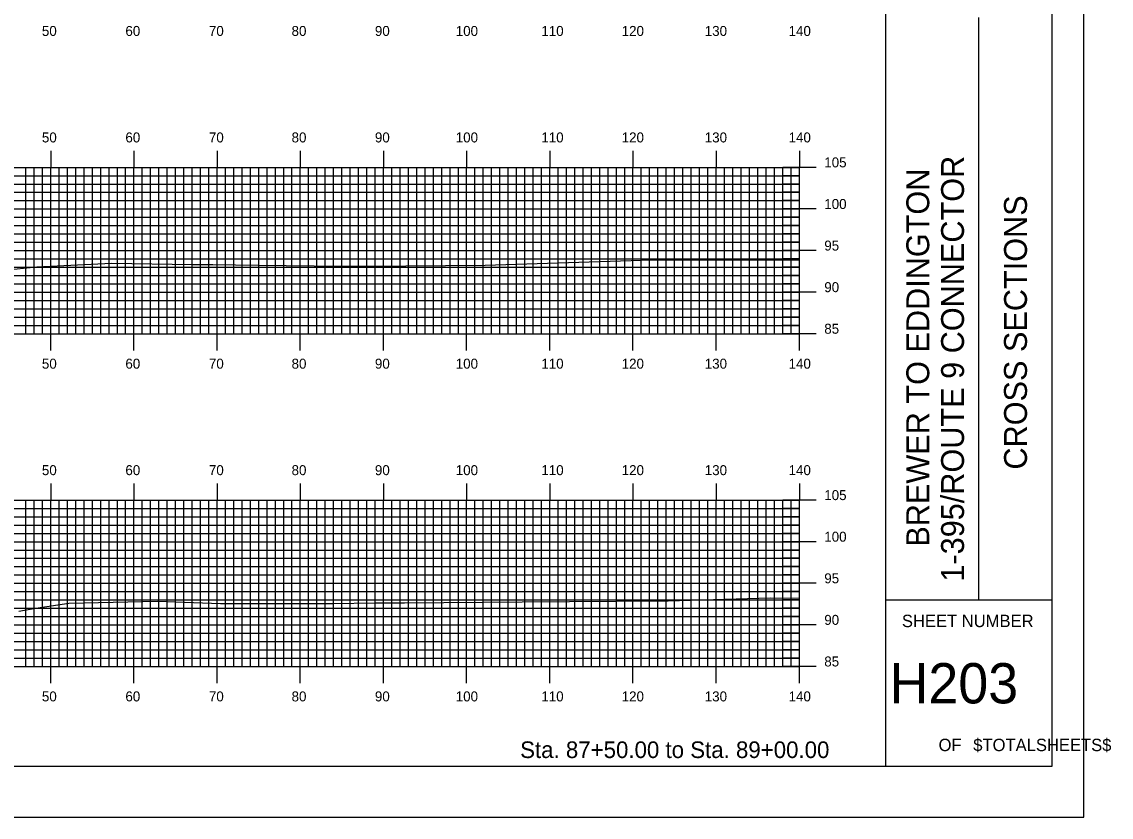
# Model space of a CAD drawing. Extents: x 1764152 to 1764495, y 442591 to 442811.
# Drawn here: x 1764364.3 to 1764495.3, y 442590.5 to 442686.2 of the extents above; entities that cross this region are included whole.
import ezdxf

# ---------------------------------------------------------------- set-up
doc = ezdxf.new("R2010")
doc.units = 0
for name, color, linetype in [('BORDER', 7, 'Continuous'), ('H_V ANNOTATION', 7, 'Continuous'), ('MAJOR', 7, 'Continuous'), ('MINOR', 7, 'Continuous'), ('PLOT BOUNDARY', 7, 'Continuous'), ('S_Roadway_Centerline', 7, 'Continuous')]:
    doc.layers.add(name, color=color, linetype=linetype)

msp = doc.modelspace()

# ---------------------------------------------------------------- linework, layer by layer
at = {"layer": 'BORDER'}
for p, q in [((1764468.23, 442596.67), (1764468.23, 442806.67)), ((1764479.41, 442616.67), (1764479.41, 442686.67)), ((1764468.23, 442616.67), (1764488.23, 442616.67))]:
    msp.add_line(p, q, dxfattribs=at)
msp.add_lwpolyline([(1764168.23, 442596.67), (1764488.23, 442596.67), (1764488.23, 442806.67), (1764168.23, 442806.67)], close=True, dxfattribs=at)
at = {"layer": 'MAJOR'}
for p, q in [((1764367.83, 442670.67), (1764367.83, 442668.67)), ((1764377.83, 442670.67), (1764377.83, 442668.67)), ((1764387.83, 442670.67), (1764387.83, 442668.67)), ((1764397.83, 442670.67), (1764397.83, 442668.67)), ((1764407.83, 442670.67), (1764407.83, 442668.67)), ((1764417.83, 442670.67), (1764417.83, 442668.67)), ((1764427.83, 442670.67), (1764427.83, 442668.67)), ((1764437.83, 442670.67), (1764437.83, 442668.67)), ((1764447.83, 442670.67), (1764447.83, 442668.67)), ((1764457.83, 442670.67), (1764457.83, 442668.67)), ((1764177.83, 442668.67), (1764457.83, 442668.67)), ((1764177.83, 442668.67), (1764457.83, 442668.67)), ((1764367.83, 442648.67), (1764367.83, 442668.67)), ((1764377.83, 442648.67), (1764377.83, 442668.67)), ((1764387.83, 442648.67), (1764387.83, 442668.67)), ((1764397.83, 442648.67), (1764397.83, 442668.67)), ((1764407.83, 442648.67), (1764407.83, 442668.67)), ((1764417.83, 442648.67), (1764417.83, 442668.67)), ((1764427.83, 442648.67), (1764427.83, 442668.67)), ((1764437.83, 442648.67), (1764437.83, 442668.67)), ((1764447.83, 442648.67), (1764447.83, 442668.67)), ((1764459.84, 442668.67), (1764455.83, 442668.67)), ((1764457.83, 442648.67), (1764457.83, 442668.67)), ((1764457.83, 442648.67), (1764457.83, 442668.67)), ((1764177.83, 442663.67), (1764457.83, 442663.67)), ((1764459.84, 442663.67), (1764455.83, 442663.67)), ((1764177.83, 442658.67), (1764457.83, 442658.67)), ((1764459.84, 442658.67), (1764455.83, 442658.67)), ((1764177.83, 442653.67), (1764457.83, 442653.67)), ((1764459.84, 442653.67), (1764455.83, 442653.67)), ((1764177.83, 442648.67), (1764457.83, 442648.67)), ((1764177.83, 442648.67), (1764457.83, 442648.67)), ((1764367.83, 442646.66), (1764367.83, 442648.67)), ((1764377.83, 442646.66), (1764377.83, 442648.67)), ((1764387.83, 442646.66), (1764387.83, 442648.67)), ((1764397.83, 442646.66), (1764397.83, 442648.67)), ((1764407.83, 442646.66), (1764407.83, 442648.67)), ((1764417.83, 442646.66), (1764417.83, 442648.67)), ((1764427.83, 442646.66), (1764427.83, 442648.67)), ((1764437.83, 442646.66), (1764437.83, 442648.67)), ((1764447.83, 442646.66), (1764447.83, 442648.67)), ((1764459.84, 442648.67), (1764455.83, 442648.67)), ((1764457.83, 442646.66), (1764457.83, 442648.67)), ((1764367.83, 442630.67), (1764367.83, 442628.67)), ((1764377.83, 442630.67), (1764377.83, 442628.67)), ((1764387.83, 442630.67), (1764387.83, 442628.67)), ((1764397.83, 442630.67), (1764397.83, 442628.67)), ((1764407.83, 442630.67), (1764407.83, 442628.67)), ((1764417.83, 442630.67), (1764417.83, 442628.67)), ((1764427.83, 442630.67), (1764427.83, 442628.67)), ((1764437.83, 442630.67), (1764437.83, 442628.67)), ((1764447.83, 442630.67), (1764447.83, 442628.67)), ((1764457.83, 442630.67), (1764457.83, 442628.67)), ((1764177.83, 442628.67), (1764457.83, 442628.67)), ((1764177.83, 442628.67), (1764457.83, 442628.67)), ((1764367.83, 442608.67), (1764367.83, 442628.67)), ((1764377.83, 442608.67), (1764377.83, 442628.67)), ((1764387.83, 442608.67), (1764387.83, 442628.67)), ((1764397.83, 442608.67), (1764397.83, 442628.67)), ((1764407.83, 442608.67), (1764407.83, 442628.67)), ((1764417.83, 442608.67), (1764417.83, 442628.67)), ((1764427.83, 442608.67), (1764427.83, 442628.67)), ((1764437.83, 442608.67), (1764437.83, 442628.67)), ((1764447.83, 442608.67), (1764447.83, 442628.67)), ((1764459.84, 442628.67), (1764455.83, 442628.67)), ((1764457.83, 442608.67), (1764457.83, 442628.67)), ((1764457.83, 442608.67), (1764457.83, 442628.67)), ((1764177.83, 442623.67), (1764457.83, 442623.67)), ((1764459.84, 442623.67), (1764455.83, 442623.67)), ((1764177.83, 442618.67), (1764457.83, 442618.67)), ((1764459.84, 442618.67), (1764455.83, 442618.67)), ((1764177.83, 442613.67), (1764457.83, 442613.67)), ((1764459.84, 442613.67), (1764455.83, 442613.67)), ((1764177.83, 442608.67), (1764457.83, 442608.67)), ((1764177.83, 442608.67), (1764457.83, 442608.67)), ((1764367.83, 442606.66), (1764367.83, 442608.67)), ((1764377.83, 442606.66), (1764377.83, 442608.67)), ((1764387.83, 442606.66), (1764387.83, 442608.67)), ((1764397.83, 442606.66), (1764397.83, 442608.67)), ((1764407.83, 442606.66), (1764407.83, 442608.67)), ((1764417.83, 442606.66), (1764417.83, 442608.67)), ((1764427.83, 442606.66), (1764427.83, 442608.67)), ((1764437.83, 442606.66), (1764437.83, 442608.67)), ((1764447.83, 442606.66), (1764447.83, 442608.67)), ((1764459.84, 442608.67), (1764455.83, 442608.67)), ((1764457.83, 442606.66), (1764457.83, 442608.67))]:
    msp.add_line(p, q, dxfattribs=at)
at = {"layer": 'MINOR'}
for p, q in [((1764364.83, 442648.67), (1764364.83, 442668.67)), ((1764365.83, 442648.67), (1764365.83, 442668.67)), ((1764366.83, 442648.67), (1764366.83, 442668.67)), ((1764368.83, 442648.67), (1764368.83, 442668.67)), ((1764369.83, 442648.67), (1764369.83, 442668.67)), ((1764370.83, 442648.67), (1764370.83, 442668.67)), ((1764371.83, 442648.67), (1764371.83, 442668.67)), ((1764372.83, 442648.67), (1764372.83, 442668.67)), ((1764373.83, 442648.67), (1764373.83, 442668.67)), ((1764374.83, 442648.67), (1764374.83, 442668.67)), ((1764375.83, 442648.67), (1764375.83, 442668.67)), ((1764376.83, 442648.67), (1764376.83, 442668.67)), ((1764378.83, 442648.67), (1764378.83, 442668.67)), ((1764379.83, 442648.67), (1764379.83, 442668.67)), ((1764380.83, 442648.67), (1764380.83, 442668.67)), ((1764381.83, 442648.67), (1764381.83, 442668.67)), ((1764382.83, 442648.67), (1764382.83, 442668.67)), ((1764383.83, 442648.67), (1764383.83, 442668.67)), ((1764384.83, 442648.67), (1764384.83, 442668.67)), ((1764385.83, 442648.67), (1764385.83, 442668.67)), ((1764386.83, 442648.67), (1764386.83, 442668.67)), ((1764388.83, 442648.67), (1764388.83, 442668.67)), ((1764389.83, 442648.67), (1764389.83, 442668.67)), ((1764390.83, 442648.67), (1764390.83, 442668.67)), ((1764391.83, 442648.67), (1764391.83, 442668.67)), ((1764392.83, 442648.67), (1764392.83, 442668.67)), ((1764393.83, 442648.67), (1764393.83, 442668.67)), ((1764394.83, 442648.67), (1764394.83, 442668.67)), ((1764395.83, 442648.67), (1764395.83, 442668.67)), ((1764396.83, 442648.67), (1764396.83, 442668.67)), ((1764398.83, 442648.67), (1764398.83, 442668.67)), ((1764399.83, 442648.67), (1764399.83, 442668.67)), ((1764400.83, 442648.67), (1764400.83, 442668.67)), ((1764401.83, 442648.67), (1764401.83, 442668.67)), ((1764402.83, 442648.67), (1764402.83, 442668.67)), ((1764403.83, 442648.67), (1764403.83, 442668.67)), ((1764404.83, 442648.67), (1764404.83, 442668.67)), ((1764405.83, 442648.67), (1764405.83, 442668.67)), ((1764406.83, 442648.67), (1764406.83, 442668.67)), ((1764408.83, 442648.67), (1764408.83, 442668.67)), ((1764409.83, 442648.67), (1764409.83, 442668.67)), ((1764410.83, 442648.67), (1764410.83, 442668.67)), ((1764411.83, 442648.67), (1764411.83, 442668.67)), ((1764412.83, 442648.67), (1764412.83, 442668.67)), ((1764413.83, 442648.67), (1764413.83, 442668.67)), ((1764414.83, 442648.67), (1764414.83, 442668.67)), ((1764415.83, 442648.67), (1764415.83, 442668.67)), ((1764416.83, 442648.67), (1764416.83, 442668.67)), ((1764418.83, 442648.67), (1764418.83, 442668.67)), ((1764419.83, 442648.67), (1764419.83, 442668.67)), ((1764420.83, 442648.67), (1764420.83, 442668.67)), ((1764421.83, 442648.67), (1764421.83, 442668.67)), ((1764422.83, 442648.67), (1764422.83, 442668.67)), ((1764423.83, 442648.67), (1764423.83, 442668.67)), ((1764424.83, 442648.67), (1764424.83, 442668.67)), ((1764425.83, 442648.67), (1764425.83, 442668.67)), ((1764426.83, 442648.67), (1764426.83, 442668.67)), ((1764428.83, 442648.67), (1764428.83, 442668.67)), ((1764429.83, 442648.67), (1764429.83, 442668.67)), ((1764430.83, 442648.67), (1764430.83, 442668.67)), ((1764431.83, 442648.67), (1764431.83, 442668.67)), ((1764432.83, 442648.67), (1764432.83, 442668.67)), ((1764433.83, 442648.67), (1764433.83, 442668.67)), ((1764434.83, 442648.67), (1764434.83, 442668.67)), ((1764435.83, 442648.67), (1764435.83, 442668.67)), ((1764436.83, 442648.67), (1764436.83, 442668.67)), ((1764438.83, 442648.67), (1764438.83, 442668.67)), ((1764439.83, 442648.67), (1764439.83, 442668.67)), ((1764440.83, 442648.67), (1764440.83, 442668.67)), ((1764441.83, 442648.67), (1764441.83, 442668.67)), ((1764442.83, 442648.67), (1764442.83, 442668.67)), ((1764443.83, 442648.67), (1764443.83, 442668.67)), ((1764444.83, 442648.67), (1764444.83, 442668.67)), ((1764445.83, 442648.67), (1764445.83, 442668.67)), ((1764446.83, 442648.67), (1764446.83, 442668.67)), ((1764448.83, 442648.67), (1764448.83, 442668.67)), ((1764449.83, 442648.67), (1764449.83, 442668.67)), ((1764450.83, 442648.67), (1764450.83, 442668.67)), ((1764451.83, 442648.67), (1764451.83, 442668.67)), ((1764452.83, 442648.67), (1764452.83, 442668.67)), ((1764453.83, 442648.67), (1764453.83, 442668.67)), ((1764454.83, 442648.67), (1764454.83, 442668.67)), ((1764455.83, 442648.67), (1764455.83, 442668.67)), ((1764456.83, 442648.67), (1764456.83, 442668.67)), ((1764177.83, 442667.67), (1764457.83, 442667.67)), ((1764177.83, 442666.67), (1764457.83, 442666.67)), ((1764457.83, 442667.67), (1764455.83, 442667.67)), ((1764457.83, 442666.67), (1764455.83, 442666.67)), ((1764177.83, 442665.67), (1764457.83, 442665.67)), ((1764457.83, 442665.67), (1764455.83, 442665.67)), ((1764177.83, 442664.67), (1764457.83, 442664.67)), ((1764457.83, 442664.67), (1764455.83, 442664.67)), ((1764177.83, 442662.67), (1764457.83, 442662.67)), ((1764457.83, 442662.67), (1764455.83, 442662.67)), ((1764177.83, 442661.67), (1764457.83, 442661.67)), ((1764457.83, 442661.67), (1764455.83, 442661.67)), ((1764177.83, 442660.67), (1764457.83, 442660.67)), ((1764457.83, 442660.67), (1764455.83, 442660.67)), ((1764177.83, 442659.67), (1764457.83, 442659.67)), ((1764457.83, 442659.67), (1764455.83, 442659.67)), ((1764177.83, 442657.67), (1764457.83, 442657.67)), ((1764457.83, 442657.67), (1764455.83, 442657.67)), ((1764177.83, 442656.67), (1764457.83, 442656.67)), ((1764457.83, 442656.67), (1764455.83, 442656.67)), ((1764177.83, 442655.67), (1764457.83, 442655.67)), ((1764177.83, 442654.67), (1764457.83, 442654.67)), ((1764457.83, 442655.67), (1764455.83, 442655.67)), ((1764457.83, 442654.67), (1764455.83, 442654.67)), ((1764177.83, 442652.67), (1764457.83, 442652.67)), ((1764457.83, 442652.67), (1764455.83, 442652.67)), ((1764177.83, 442651.67), (1764457.83, 442651.67)), ((1764457.83, 442651.67), (1764455.83, 442651.67)), ((1764177.83, 442650.67), (1764457.83, 442650.67)), ((1764177.83, 442649.67), (1764457.83, 442649.67)), ((1764457.83, 442650.67), (1764455.83, 442650.67)), ((1764457.83, 442649.67), (1764455.83, 442649.67)), ((1764364.83, 442608.67), (1764364.83, 442628.67)), ((1764365.83, 442608.67), (1764365.83, 442628.67)), ((1764366.83, 442608.67), (1764366.83, 442628.67)), ((1764368.83, 442608.67), (1764368.83, 442628.67)), ((1764369.83, 442608.67), (1764369.83, 442628.67)), ((1764370.83, 442608.67), (1764370.83, 442628.67)), ((1764371.83, 442608.67), (1764371.83, 442628.67)), ((1764372.83, 442608.67), (1764372.83, 442628.67)), ((1764373.83, 442608.67), (1764373.83, 442628.67)), ((1764374.83, 442608.67), (1764374.83, 442628.67)), ((1764375.83, 442608.67), (1764375.83, 442628.67)), ((1764376.83, 442608.67), (1764376.83, 442628.67)), ((1764378.83, 442608.67), (1764378.83, 442628.67)), ((1764379.83, 442608.67), (1764379.83, 442628.67)), ((1764380.83, 442608.67), (1764380.83, 442628.67)), ((1764381.83, 442608.67), (1764381.83, 442628.67)), ((1764382.83, 442608.67), (1764382.83, 442628.67)), ((1764383.83, 442608.67), (1764383.83, 442628.67)), ((1764384.83, 442608.67), (1764384.83, 442628.67)), ((1764385.83, 442608.67), (1764385.83, 442628.67)), ((1764386.83, 442608.67), (1764386.83, 442628.67)), ((1764388.83, 442608.67), (1764388.83, 442628.67)), ((1764389.83, 442608.67), (1764389.83, 442628.67)), ((1764390.83, 442608.67), (1764390.83, 442628.67)), ((1764391.83, 442608.67), (1764391.83, 442628.67)), ((1764392.83, 442608.67), (1764392.83, 442628.67)), ((1764393.83, 442608.67), (1764393.83, 442628.67)), ((1764394.83, 442608.67), (1764394.83, 442628.67)), ((1764395.83, 442608.67), (1764395.83, 442628.67)), ((1764396.83, 442608.67), (1764396.83, 442628.67)), ((1764398.83, 442608.67), (1764398.83, 442628.67)), ((1764399.83, 442608.67), (1764399.83, 442628.67)), ((1764400.83, 442608.67), (1764400.83, 442628.67)), ((1764401.83, 442608.67), (1764401.83, 442628.67)), ((1764402.83, 442608.67), (1764402.83, 442628.67)), ((1764403.83, 442608.67), (1764403.83, 442628.67)), ((1764404.83, 442608.67), (1764404.83, 442628.67)), ((1764405.83, 442608.67), (1764405.83, 442628.67)), ((1764406.83, 442608.67), (1764406.83, 442628.67)), ((1764408.83, 442608.67), (1764408.83, 442628.67)), ((1764409.83, 442608.67), (1764409.83, 442628.67)), ((1764410.83, 442608.67), (1764410.83, 442628.67)), ((1764411.83, 442608.67), (1764411.83, 442628.67)), ((1764412.83, 442608.67), (1764412.83, 442628.67)), ((1764413.83, 442608.67), (1764413.83, 442628.67)), ((1764414.83, 442608.67), (1764414.83, 442628.67)), ((1764415.83, 442608.67), (1764415.83, 442628.67)), ((1764416.83, 442608.67), (1764416.83, 442628.67)), ((1764418.83, 442608.67), (1764418.83, 442628.67)), ((1764419.83, 442608.67), (1764419.83, 442628.67)), ((1764420.83, 442608.67), (1764420.83, 442628.67)), ((1764421.83, 442608.67), (1764421.83, 442628.67)), ((1764422.83, 442608.67), (1764422.83, 442628.67)), ((1764423.83, 442608.67), (1764423.83, 442628.67)), ((1764424.83, 442608.67), (1764424.83, 442628.67)), ((1764425.83, 442608.67), (1764425.83, 442628.67)), ((1764426.83, 442608.67), (1764426.83, 442628.67)), ((1764428.83, 442608.67), (1764428.83, 442628.67)), ((1764429.83, 442608.67), (1764429.83, 442628.67)), ((1764430.83, 442608.67), (1764430.83, 442628.67)), ((1764431.83, 442608.67), (1764431.83, 442628.67)), ((1764432.83, 442608.67), (1764432.83, 442628.67)), ((1764433.83, 442608.67), (1764433.83, 442628.67)), ((1764434.83, 442608.67), (1764434.83, 442628.67)), ((1764435.83, 442608.67), (1764435.83, 442628.67)), ((1764436.83, 442608.67), (1764436.83, 442628.67)), ((1764438.83, 442608.67), (1764438.83, 442628.67)), ((1764439.83, 442608.67), (1764439.83, 442628.67)), ((1764440.83, 442608.67), (1764440.83, 442628.67)), ((1764441.83, 442608.67), (1764441.83, 442628.67)), ((1764442.83, 442608.67), (1764442.83, 442628.67)), ((1764443.83, 442608.67), (1764443.83, 442628.67)), ((1764444.83, 442608.67), (1764444.83, 442628.67)), ((1764445.83, 442608.67), (1764445.83, 442628.67)), ((1764446.83, 442608.67), (1764446.83, 442628.67)), ((1764448.83, 442608.67), (1764448.83, 442628.67)), ((1764449.83, 442608.67), (1764449.83, 442628.67)), ((1764450.83, 442608.67), (1764450.83, 442628.67)), ((1764451.83, 442608.67), (1764451.83, 442628.67)), ((1764452.83, 442608.67), (1764452.83, 442628.67)), ((1764453.83, 442608.67), (1764453.83, 442628.67)), ((1764454.83, 442608.67), (1764454.83, 442628.67)), ((1764455.83, 442608.67), (1764455.83, 442628.67)), ((1764456.83, 442608.67), (1764456.83, 442628.67)), ((1764177.83, 442627.67), (1764457.83, 442627.67)), ((1764457.83, 442627.67), (1764455.83, 442627.67)), ((1764177.83, 442626.67), (1764457.83, 442626.67)), ((1764457.83, 442626.67), (1764455.83, 442626.67)), ((1764177.83, 442625.67), (1764457.83, 442625.67)), ((1764177.83, 442624.67), (1764457.83, 442624.67)), ((1764457.83, 442625.67), (1764455.83, 442625.67)), ((1764457.83, 442624.67), (1764455.83, 442624.67)), ((1764177.83, 442622.67), (1764457.83, 442622.67)), ((1764457.83, 442622.67), (1764455.83, 442622.67)), ((1764177.83, 442621.67), (1764457.83, 442621.67)), ((1764177.83, 442620.67), (1764457.83, 442620.67)), ((1764457.83, 442621.67), (1764455.83, 442621.67)), ((1764457.83, 442620.67), (1764455.83, 442620.67)), ((1764177.83, 442619.67), (1764457.83, 442619.67)), ((1764457.83, 442619.67), (1764455.83, 442619.67)), ((1764177.83, 442617.67), (1764457.83, 442617.67)), ((1764457.83, 442617.67), (1764455.83, 442617.67)), ((1764177.83, 442616.67), (1764457.83, 442616.67)), ((1764177.83, 442615.67), (1764457.83, 442615.67)), ((1764457.83, 442616.67), (1764455.83, 442616.67)), ((1764457.83, 442615.67), (1764455.83, 442615.67)), ((1764177.83, 442614.67), (1764457.83, 442614.67)), ((1764457.83, 442614.67), (1764455.83, 442614.67)), ((1764177.83, 442612.67), (1764457.83, 442612.67)), ((1764177.83, 442611.67), (1764457.83, 442611.67)), ((1764457.83, 442612.67), (1764455.83, 442612.67)), ((1764457.83, 442611.67), (1764455.83, 442611.67)), ((1764177.83, 442610.67), (1764457.83, 442610.67)), ((1764457.83, 442610.67), (1764455.83, 442610.67)), ((1764177.83, 442609.67), (1764457.83, 442609.67)), ((1764457.83, 442609.67), (1764455.83, 442609.67))]:
    msp.add_line(p, q, dxfattribs=at)
at = {"layer": 'PLOT BOUNDARY'}
msp.add_lwpolyline([(1764152.04, 442590.55), (1764492.04, 442590.55), (1764492.04, 442810.55), (1764152.04, 442810.55)], close=True, dxfattribs=at)
at = {"layer": 'S_Roadway_Centerline'}
for points in [[(1764362.2, 442656.33), (1764366.15, 442656.7), (1764375.14, 442657.16), (1764384.85, 442657), (1764387.3, 442657.01), (1764392.75, 442656.93), (1764402.86, 442656.81), (1764410.5, 442656.85), (1764420.05, 442656.91), (1764432.55, 442657.32), (1764438.86, 442657.52), (1764449.62, 442657.56), (1764456.54, 442657.54), (1764457.83, 442657.55)], [(1764363.99, 442615.31), (1764366.02, 442615.67), (1764369.98, 442616.26), (1764380.66, 442616.5), (1764388.24, 442616.22), (1764401.82, 442616.25), (1764406.73, 442616.3), (1764410.37, 442616.33), (1764424.51, 442616.43), (1764441.56, 442616.55), (1764441.78, 442616.56), (1764442.06, 442616.56), (1764454.34, 442616.93), (1764457.83, 442616.9)]]:
    msp.add_lwpolyline(points, dxfattribs=at)

# ---------------------------------------------------------------- texts
at = {"layer": 'BORDER'}
for s, p in [('1-395/ROUTE 9 CONNECTOR', (1764477.63, 442618.87)), ('BREWER TO EDDINGTON', (1764473.45, 442623.07)), ('CROSS SECTIONS', (1764485.2, 442632.34))]:
    msp.add_text(s, height=2.7557, rotation=90, dxfattribs=at).set_placement(p)
for s, height, p in [('SHEET NUMBER', 1.4905, (1764470.16, 442613.4)), ('H203', 4.839, (1764468.67, 442604.23)), ('OF', 1.491, (1764474.57, 442598.49)), ('$TOTALSHEETS$', 1.4905, (1764478.74, 442598.49))]:
    msp.add_text(s, height=height, dxfattribs=at).set_placement(p)
at = {"layer": 'H_V ANNOTATION'}
for s, height, p in [('50', 1.2, (1764366.76, 442684.47)), ('60', 1.2, (1764376.8, 442684.47)), ('70', 1.2, (1764386.84, 442684.47)), ('80', 1.2, (1764396.78, 442684.47)), ('90', 1.2, (1764406.8, 442684.47)), ('100', 1.2, (1764416.52, 442684.47)), ('110', 1.2, (1764426.81, 442684.47)), ('120', 1.2, (1764436.47, 442684.47)), ('130', 1.2, (1764446.46, 442684.47)), ('140', 1.2, (1764456.54, 442684.47)), ('50', 1.2, (1764366.76, 442671.67)), ('60', 1.2, (1764376.8, 442671.67)), ('70', 1.2, (1764386.84, 442671.67)), ('80', 1.2, (1764396.78, 442671.67)), ('90', 1.2, (1764406.8, 442671.67)), ('100', 1.2, (1764416.52, 442671.67)), ('110', 1.2, (1764426.81, 442671.67)), ('120', 1.2, (1764436.47, 442671.67)), ('130', 1.2, (1764446.46, 442671.67)), ('140', 1.2, (1764456.54, 442671.67)), ('105', 1.2, (1764460.83, 442668.67)), ('100', 1.2, (1764460.83, 442663.67)), ('95', 1.2, (1764460.83, 442658.67)), ('90', 1.2, (1764460.83, 442653.67)), ('85', 1.2, (1764460.83, 442648.67)), ('50', 1.2, (1764366.76, 442644.47)), ('60', 1.2, (1764376.8, 442644.47)), ('70', 1.2, (1764386.84, 442644.47)), ('80', 1.2, (1764396.78, 442644.47)), ('90', 1.2, (1764406.8, 442644.47)), ('100', 1.2, (1764416.52, 442644.47)), ('110', 1.2, (1764426.81, 442644.47)), ('120', 1.2, (1764436.47, 442644.47)), ('130', 1.2, (1764446.46, 442644.47)), ('140', 1.2, (1764456.54, 442644.47)), ('50', 1.2, (1764366.76, 442631.67)), ('60', 1.2, (1764376.8, 442631.67)), ('70', 1.2, (1764386.84, 442631.67)), ('80', 1.2, (1764396.78, 442631.67)), ('90', 1.2, (1764406.8, 442631.67)), ('100', 1.2, (1764416.52, 442631.67)), ('110', 1.2, (1764426.81, 442631.67)), ('120', 1.2, (1764436.47, 442631.67)), ('130', 1.2, (1764446.46, 442631.67)), ('140', 1.2, (1764456.54, 442631.67)), ('105', 1.2, (1764460.83, 442628.67)), ('100', 1.2, (1764460.83, 442623.67)), ('95', 1.2, (1764460.83, 442618.67)), ('90', 1.2, (1764460.83, 442613.67)), ('85', 1.2, (1764460.83, 442608.67)), ('50', 1.2, (1764366.76, 442604.47)), ('60', 1.2, (1764376.8, 442604.47)), ('70', 1.2, (1764386.84, 442604.47)), ('80', 1.2, (1764396.78, 442604.47)), ('90', 1.2, (1764406.8, 442604.47)), ('100', 1.2, (1764416.52, 442604.47)), ('110', 1.2, (1764426.81, 442604.47)), ('120', 1.2, (1764436.47, 442604.47)), ('130', 1.2, (1764446.46, 442604.47)), ('140', 1.2, (1764456.54, 442604.47)), ('Sta. 87+50.00 to Sta. 89+00.00', 2.0004, (1764424.26, 442597.66))]:
    msp.add_text(s, height=height, dxfattribs=at).set_placement(p)

doc.saveas('drawing.dxf')
